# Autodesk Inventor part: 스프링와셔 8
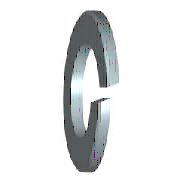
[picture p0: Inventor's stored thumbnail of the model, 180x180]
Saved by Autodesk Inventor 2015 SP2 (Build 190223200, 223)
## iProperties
IsCustomPart: 1
Created: 2012-02
Part Number: 스프링와셔 8
Material: 강철, 연강
Description: 스프링 잠금 와셔
Document SubType Name: Modeling
Standard: KS B 1324
Designer: mduedu
Standards Organization: KS
Language: ko-KR
Size Designation: 번호 3 - 8
Categories: <MemberInstance><Categories><Category DisplayName="조임쇠" InternalName="e4da775c-781d-43d5-af7c-5136215cf5a6" Mnemonic="FSTN"><Category DisplayName="와셔" InternalN
Density: 1 g/cm^3
Appearance: 파란색 - 벽 페인트 - 광택
Author: mduedu
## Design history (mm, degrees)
sketch "스케치1"
  geometry: C1 r 7.4 at (0, 0); C2 r 4.1 at (0, 0); 1 further point
  constraints: 2 centre point, 2 coincident
  dimensions: "d0" = 8.2 diameter of C2 (= SD1); "d1" = 14.8 diameter of C1 (= SD2)
extrude "본체" new body sketch "스케치1" distance "d2" = 2.5 (= SD); taper "d3" = 0 deg
sketch "스케치2"
  geometry: L1 (0, -4.1)-(0, 4.1) reference; L2 (2.5, 7.4)-(2.5, -7.4) reference; L3 (-1.2, 0)-(7.2, 0) reference; L4 (0, -0.5)-(2.5, 0.41); L5 (0, 0.5)-(2.5, 1.41)
  constraints: 4 end point, 4 point on line, 1 parallel
  dimensions: "d4" = 0.5 distance from line of L3 L4.start (= 0.2 x SD); "d5" = 0.5 distance from line of L3 L5.start (= 0.2 x SD); "d6" = 70 deg angle of L2 L4 (= FAWI)
extrude "절단부" cut sketch "스케치2" stored distance "d7" = 2.5 (= SD); taper "d8" = 0 deg
workaxis "Work Axis1"
workplane "Work Plane1"
body "Solid1"
other parameters: "SD1" = 8.2 [user parameter; used in 1 equation term], "SD2" = 14.8 [user parameter; used in 1 equation term], "SD" = 2.5 [user parameter; used in 4 equation terms], "FAWI" = 70 deg [user parameter; used in 1 equation term], "d9" = 0, "d10" = 0, "d11" = 0, "d12" = 0, "SDI" = 3.3 [user parameter], "NND" = 8 [user parameter]
